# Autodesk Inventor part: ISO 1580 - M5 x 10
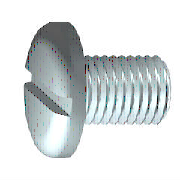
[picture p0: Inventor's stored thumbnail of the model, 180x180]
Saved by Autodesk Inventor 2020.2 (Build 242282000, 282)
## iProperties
Created: 2019-01
Part Number: ISO 1580 - M5 x 10
Material: Stal, miękka
Description: Wkręt z łbem walcowym wypukłym z rowkiem prostym - klasa produkcyjna A
Document SubType Name: Modeling
Standard: ISO 1580
Designer: F.Stasiak
Standard Revision: Third edition 2011-09-01
Standards Organization: ISO
Language: pl-PL
Size Designation: M5 x 10
Categories: <MemberInstance><Categories><Category DisplayName="Mocowania" InternalName="e4da775c-781d-43d5-af7c-5136215cf5a6" Mnemonic="FSTN"><Category DisplayName="Śruby"
Density: 7.85 g/cm^3
Appearance: Częściowo polerowany
Manager: www.cadconsulting.pl
Company: Fabian Stasiak CAD Consulting
IsCustomPart: 0
Author: F.Stasiak
Subject: Zbiór ćwiczeń. Autodesk Inventor 2020. Kurs podstawowy
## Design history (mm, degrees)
body "Solid1"
revolve "Bryła" stored, may be unused: angle "d8" = 90 deg
sketch "Szkic2"
  geometry: L1 (0, 0)-(0, 4.488) reference; L2 (-4.75, 0.6)-(4.75, 0.6); L3 (4.75, 0.6)-(4.75, -0.6); L4 (4.75, -0.6)-(-4.75, -0.6); L5 (-4.75, -0.6)-(-4.75, 0.6); L6 (-4.75, 0)-(4.75, 0); L7 (0, 0.6)-(0, -0.6); C1 r 4.75 at (0, 0) reference; 1 further point
  constraints: 12 end point, 5 midpoint, 2 parallel, 1 collinear, 1 horizontal, 1 perpendicular
  dimensions: "d11" = 1.2 distance of L4.end L2.start (= SBR); "d12" = 9.5 distance of L2.start L2.end (= KOD)
fillet "Zaokrąglenie1" dims "d14" = 1.5 (= RR)
extrude "Szczelina" cut sketch "Szkic2" distance "d19" = 1.2 (= STI); taper "d20" = 0 deg
feature "Gwint" dims "d15" = 8.4 (= GEL), "d16" = 0
workplane "Work Plane1"
fillet "Fillet5" dims "d41" = 0.2 (= R)
sketch "Szkic1"
  geometry: L1 (-3, 0)-(10, 0); L2 (10, 0)-(10, 2.5); L3 (10, 2.5)-(1.6, 2.5); L4 (1.6, 2.5)-(1.109, 2.255); L5 (1.109, 2.255)-(0, 2.255); L6 (0, 2.255)-(0, 4.75); L7 (-5.6, 0)-(12.6, 0) reference; L8 (0, -0.95)-(0, 5.7) reference; L9 (-3, 0)-(-3, 4.488); L10 (0, 4.75)-(-3, 4.488); L11 (1.6, 2.5)-(0, 2.5)
  constraints: 18 end point, 4 parallel, 2 collinear, 2 perpendicular, 1 horizontal, 1 point on line
  dimensions: "d0" = 10 distance between parallel lines of L2 L6 (= NLG); "d1" = 8.4 distance from line of L3.end L2 (= GEL); "d2" = 0.49086 horizontal distance of L4.end L3.end (computed from GAL); "d3" = 3 distance from line of L1.start L6 (= KOH); "d4" = 5 diameter of L3 L1 (= GD); "d5" = 4.5095 diameter of L5 L1 (= BDM); "d9" = 9.5 diameter of L6.end L1 (= KOD); "d10" = 5 deg angle of L10 L1 (= KEWI)
other parameters: "GD" = 5 (= NND) [user parameter; used in 1 equation term], "NLG" = 10 [user parameter; used in 1 equation term], "GEL" = 8.4 [user parameter; used in 2 equation terms], "KOD" = 9.5 [user parameter; used in 2 equation terms], "KOH" = 3 [user parameter; used in 1 equation term], "GAL" = 0.49076 (= 0.61345 x PTC) [user parameter; used in 1 equation term], "R" = 0.2 [user parameter; used in 1 equation term], "BDM" = 4.5095 [user parameter; used in 1 equation term], "GUL" = 0.49076 (= 0.61345 x PTC) [user parameter], "RR" = 1.5 [user parameter; used in 1 equation term], "d7" = 0, "SBR" = 1.2 [user parameter; used in 1 equation term], "STI" = 1.2 [user parameter; used in 1 equation term], "KEWI" = 5 deg [user parameter; used in 1 equation term], "d37" = 0, "d39" = 0, "PTC" = 0.8 [user parameter; used in 4 equation terms], "THREADDIA" = 5 [user parameter; used in 1 equation term], "TOA" = 30 deg [user parameter], "TPU" = 12.5 (computed from PTC) [user parameter], "NND" = 5 [user parameter; used in 1 equation term], "GD1" = 4.01848 (= THREADDIA - 1.2269 x PTC) [user parameter]
